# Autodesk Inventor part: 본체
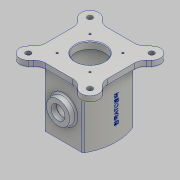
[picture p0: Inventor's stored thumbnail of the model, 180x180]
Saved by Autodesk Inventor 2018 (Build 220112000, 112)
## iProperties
Created: 2022-01
Part Number: 본체
Material: 알루미늄 6061
Document SubType Name: Modeling
Designer: home
Density: 2.7 g/cm^3
Appearance: 알루미늄 - 평지
Mass: 1228.11 g
Surface Area: 921.714 cm^2
Volume: 454.856 cm^3
Author: home
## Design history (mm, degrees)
sketch "스케치1"
  geometry: L1 (31.191, -45)-(-31.191, -45); A1 r 90 centre (45, 0) between (-37.506, 35.954) and (-33.818, -43.448); A2 r 90 centre (-45, 0) between (33.818, -43.448) and (37.506, 35.954); A3 r 90 centre (0, -45) between (35.954, 37.506) and (-35.954, 37.506); A4 r 3 centre (31.191, -42) between (31.191, -45) and (33.818, -43.448); A5 r 3 centre (-31.191, -42) between (-33.818, -43.448) and (-31.191, -45); A6 r 3 centre (-34.756, 34.756) between (-35.954, 37.506) and (-37.506, 35.954); A7 r 3 centre (34.756, 34.756) between (37.506, 35.954) and (35.954, 37.506); 3 further points
  constraints: 17 point on circle, 8 tangent, 7 centre point, 3 equal radius, 2 end point, 2 point on line, 1 midpoint
  dimensions: "d3" = 45 distance from line of point (0, 0) L1; "d11" = 90 distance edge to line of A3 L1; "d12" = 90 distance of A2.centre A1.centre; "d13" = 45 distance of A3.centre point (0, 0); "d16" = 45 distance of point (0, 0) A1.centre; "d17" = 45 distance of A2.centre point (0, 0); "d18" = 45 distance from line of L1 A2.centre; "d19" = 90 radius of A2; "d20" = 3 radius of A4; "d83" = 31.19055 horizontal distance of point (0, 0) A4.centre
extrude "돌출1" new body sketch "스케치1" stored distance "d21" = 98; taper "d22" = 0 deg
sketch "스케치2"
  geometry: L1 (-53, 53)-(53, 53); L2 (53, 53)-(53, -53); L3 (53, -53)-(-53, -53); L4 (-53, -53)-(-53, 53); L5 (-31.191, -45)-(31.191, -45) reference; A1 r 3 centre (31.191, -42) between (31.191, -45) and (33.818, -43.448) reference; A2 r 90 centre (-45, 0) between (33.818, -43.448) and (37.506, 35.954) reference; A3 r 3 centre (34.756, 34.756) between (37.506, 35.954) and (35.954, 37.506) reference; A4 r 90 centre (0, -45) between (35.954, 37.506) and (-35.954, 37.506) reference; A5 r 3 centre (-34.756, 34.756) between (-35.954, 37.506) and (-37.506, 35.954) reference; A6 r 90 centre (45, 0) between (-37.506, 35.954) and (-33.818, -43.448) reference; A7 r 3 centre (-31.191, -42) between (-33.818, -43.448) and (-31.191, -45) reference; 1 further point
  constraints: 8 end point, 2 parallel, 1 horizontal, 1 perpendicular
  dimensions: "d23" = 106 distance between parallel lines of L4 L2; "d24" = 53 distance from line of L2 point (0, 0); "d25" = 106 distance between parallel lines of L3 L1; "d26" = 53 distance from line of L3 point (0, 0)
extrude "돌출2" join sketch "스케치2" distance "d31" = 12; taper "d32" = 0 deg
sketch "스케치3" dims "d33" = 150
  geometry: L1 (0, 0)-(-113.388, 113.388); L2 (0, 0)-(-112.107, 0); L3 (-42.426, 63.64)-(-31.787, 53); L4 (-63.64, 42.426)-(-53, 31.787); L5 (-53, 53)-(-53, -53) reference; L6 (53, 53)-(-53, 53) reference; A1 r 15 centre (-53.033, 53.033) between (-42.426, 63.64) and (-63.64, 42.426); 2 further points
  constraints: 8 end point, 3 point on line, 2 coincident, 2 parallel, 2 point on circle, 1 centre point, 1 horizontal, 3 other
  dimensions: "d34" = 45 deg angle of L1 L2; "d36" = 15 distance between parallel lines of L3 L1; "d37" = 15 distance between parallel lines of L4 L1; "d38" = 15 radius of A1
extrude "돌출3" join sketch "스케치3" distance "d39" = 12; taper "d40" = 0 deg
fillet "모깎기1" dims "d44" = 20
sketch "스케치4"
  geometry: A1 r 15 centre (-53.033, 53.033) between (-42.426, 63.64) and (-63.64, 42.426) reference; 2 further points
  constraints: 1 coincident
hole "구멍1" sketch "스케치4" at (-53.033, 53.033) diameter "d45" = 9; stored, may be unused: countersink angle "d49" = 90 deg, drill point angle "d51" = 118 deg; dims "d46" = 6, "d47" = 18, "d48" = 2, "d50" = 8
sketch "스케치7"
  geometry: L1 (0, 0)-(0, 151.16); L2 (25, -49)-(25, -37); L3 (25, -37)-(37, -37); L4 (37, -37)-(37, 49); L5 (37, 49)-(25, 49); L6 (25, 49)-(25, 61); L7 (25, -49)-(0, -49); L8 (0, -49)-(0, 61); L9 (25, 61)-(0, 61)
  constraints: 18 end point, 3 perpendicular, 3 point on line, 2 vertical, 1 horizontal
  dimensions: "d58" = 50 diameter of L6 L1; "d59" = 74 diameter of L4 L1; "d60" = 86 distance of L3.end L4.end; "d61" = 12 distance between parallel lines of L9 L5; "d62" = 49 distance from line of L7 L1.start; "d63" = 61 distance from line of L9 L1.start
revolve "회전1" sketch "스케치7" stored, may be unused: angle "d64" = 90 deg
fillet "모깎기2" dims "d65" = 3
chamfer "모따기1" distance "d66" = 1; stored, may be unused: second distance "d67" = 2, angle "d68" = 45 deg
node "작업 평면3"
sketch "스케치10"
  geometry: L1 (23.503, 61)-(-23.503, 61) reference; C1 r 20 at (0, 0); 1 further point
  constraints: 1 centre point, 1 coincident
  dimensions: "d74" = 20 radius of C1
extrude "돌출4" join sketch "스케치10" stored distance "d76" = 12; taper "d77" = 10 deg
node "작업 평면4"
sketch "스케치11"
  geometry: 2 further points
  constraints: 1 coincident, 1 other
feature "엠보싱1" sketch "스케치11" dims "d80" = 0.5, "d81" = 0
sketch "스케치12"
  geometry: L1 (-35, -15)-(-45, -15); L2 (-42, -12)-(-42, -12); L3 (-46, -12)-(-55, -12); L4 (-55, 20)-(-55, -20) reference; L5 (-55, -12)-(-55, 0); L6 (-55, 0)-(-35, 0); L7 (-35, 0)-(-35, -15); L8 (0, 0)-(-30.068, 0); L9 (-42, -15)-(-42, -15); L10 (-45, -13)-(-45, -15); L11 (-45, -49)-(-45, 49) reference; L12 (-45, -13)-(-46, -12); 1 further point
  constraints: 20 end point, 6 point on line, 3 perpendicular, 2 horizontal, 1 midpoint, 1 vertical
  dimensions: "d84" = 30 diameter of L1 L8; "d85" = 24 diameter of L3 L8; "d86" = 13 distance of L2.end L3.end; "d114" = 10 distance of L1.end L1.start; "d117" = 10 distance of point (-45, -12) L3.end; "d118" = 1 distance of L10.start point (-45, -12); "d119" = 1 distance of L3.start point (-45, -12) (= d118)
revolve "회전2" sketch "스케치12" stored, may be unused: angle "d87" = 90 deg
sketch "스케치13" dims "d89" = 40
  geometry: L1 (0, 0)-(73.114, 0); 2 further points
  constraints: 2 end point, 1 coincident, 1 horizontal, 3 other
  dimensions: "d90" = 45 deg dimension on L1.start L1.end point (28.284, -28.284)
hole "구멍2" sketch "스케치13" at (28.284, -28.284) diameter "d91" = 3.242; stored, may be unused: countersink angle "d95" = 90 deg, drill point angle "d97" = 118 deg; dims "d92" = 9, "d93" = 18, "d94" = 2, "d96" = 11
sketch "스케치14"
  geometry: L1 (0, 0)-(28.284, -28.284); L2 (23.503, 53)-(-23.503, 53) reference; C1 r 1.621 at (28.284, -28.284) reference; 1 further point
  constraints: 2 end point, 1 coincident
  dimensions: "d101" = 40 distance of L1.start L1.end; "d102" = 45 deg angle of L2 L1
hole "구멍3" sketch "스케치14" at (28.284, -28.284) diameter "d103" = 3.242; stored, may be unused: countersink angle "d107" = 90 deg, drill point angle "d109" = 118 deg; dims "d104" = 9, "d105" = 18, "d106" = 2, "d108" = 11
fillet "모깎기3" dims "d113" = 3
node "솔리드1"
pattern_circular "원형 패턴1" dims angle "d42" = 360 deg
pattern_circular "원형 패턴2" dims angle "d53" = 360 deg
pattern_circular "원형 패턴3" dims angle "d99" = 360 deg
pattern_circular "원형 패턴4" dims angle "d111" = 360 deg
node "투영된 루프1"
node "작업축1"
node "작업축2"
node "작업축3"
node "작업축4"
node "작업축5"
node "작업축6"
other parameters: "d35" = 15, "d73" = -55, "d79" = 78.5
